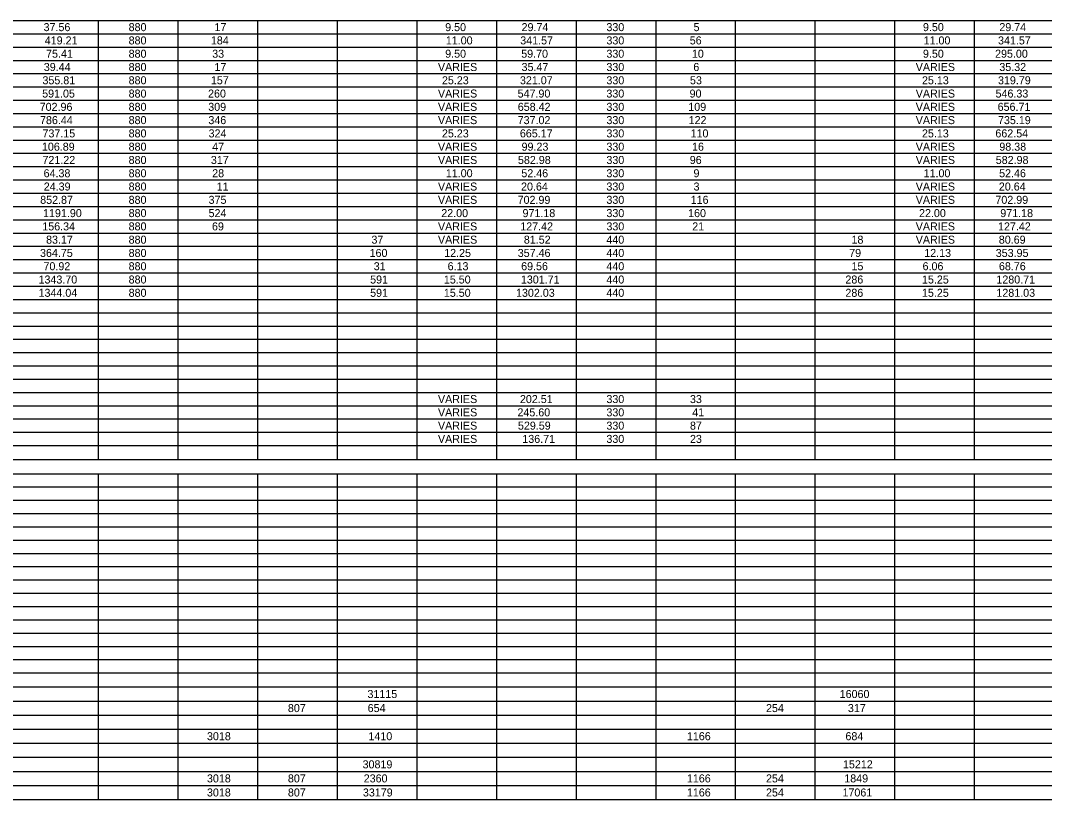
# Model space of a CAD drawing. Extents: x 1226567 to 1228151, y 151309 to 152305.
# Drawn here: x 1227158 to 1227669, y 151665 to 152053 of the extents above; entities that cross this region are included whole.
import ezdxf

# ---------------------------------------------------------------- set-up
doc = ezdxf.new("R2010")
doc.units = 0
doc.layers.add('R_Dimension', color=7, linetype='Continuous')

msp = doc.modelspace()

# ---------------------------------------------------------------- linework, layer by layer
at = {"layer": 'R_Dimension'}
for p, q in [((1226566.84, 152052.93), (1228150.79, 152052.93)), ((1227197.38, 151834.06), (1227197.38, 152052.93)), ((1227237.11, 151834.06), (1227237.11, 152052.93)), ((1227276.83, 151834.06), (1227276.83, 152052.93)), ((1227316.56, 151834.06), (1227316.56, 152052.93)), ((1227356.28, 151834.06), (1227356.28, 152052.93)), ((1227396.01, 151834.06), (1227396.01, 152052.93)), ((1227435.73, 151834.06), (1227435.73, 152052.93)), ((1227475.46, 151834.06), (1227475.46, 152052.93)), ((1227515.18, 151834.06), (1227515.18, 152052.93)), ((1227554.91, 151834.06), (1227554.91, 152052.93)), ((1227594.63, 151834.06), (1227594.63, 152052.93)), ((1227634.36, 151834.06), (1227634.36, 152052.93)), ((1226566.84, 152046.31), (1228150.79, 152046.31)), ((1226566.84, 152039.69), (1228150.79, 152039.69)), ((1226566.84, 152033.07), (1228150.79, 152033.07)), ((1226566.84, 152026.45), (1228150.79, 152026.45)), ((1226566.84, 152019.83), (1228150.79, 152019.83)), ((1226566.84, 152013.21), (1228150.79, 152013.21)), ((1226566.84, 152006.59), (1228150.79, 152006.59)), ((1226566.84, 151999.97), (1228150.79, 151999.97)), ((1226566.84, 151993.35), (1228150.79, 151993.35)), ((1226566.84, 151986.73), (1228150.79, 151986.73)), ((1226566.84, 151980.1), (1228150.79, 151980.1)), ((1226566.84, 151973.48), (1228150.79, 151973.48)), ((1226566.84, 151966.86), (1228150.79, 151966.86)), ((1226566.84, 151960.24), (1228150.79, 151960.24)), ((1226566.84, 151953.62), (1228150.79, 151953.62)), ((1226566.84, 151947), (1228150.79, 151947)), ((1226566.84, 151940.38), (1228150.79, 151940.38)), ((1226566.84, 151933.76), (1228150.79, 151933.76)), ((1226566.84, 151927.14), (1228150.79, 151927.14)), ((1226566.84, 151920.52), (1228150.79, 151920.52)), ((1226566.84, 151913.9), (1228150.79, 151913.9)), ((1226566.84, 151907.27), (1228150.79, 151907.27)), ((1226566.84, 151900.65), (1228150.79, 151900.65)), ((1226566.84, 151894.03), (1228150.79, 151894.03)), ((1226566.84, 151887.41), (1228150.79, 151887.41)), ((1226566.84, 151880.79), (1228150.79, 151880.79)), ((1226566.84, 151874.17), (1228150.79, 151874.17)), ((1226566.84, 151867.55), (1228150.79, 151867.55)), ((1226566.84, 151860.93), (1228150.79, 151860.93)), ((1226566.84, 151854.31), (1228150.79, 151854.31)), ((1226566.84, 151847.69), (1228150.79, 151847.69)), ((1226566.84, 151841.07), (1228150.79, 151841.07)), ((1226566.84, 151834.06), (1228150.79, 151834.06)), ((1226566.84, 151827.05), (1228150.79, 151827.05)), ((1227197.38, 151664.64), (1227197.38, 151827.05)), ((1227237.11, 151664.64), (1227237.11, 151827.05)), ((1227276.83, 151664.64), (1227276.83, 151827.05)), ((1227316.56, 151664.64), (1227316.56, 151827.05)), ((1227356.28, 151664.64), (1227356.28, 151827.05)), ((1227396.01, 151664.64), (1227396.01, 151827.05)), ((1227435.73, 151664.64), (1227435.73, 151827.05)), ((1227475.46, 151664.64), (1227475.46, 151827.05)), ((1227515.18, 151664.64), (1227515.18, 151827.05)), ((1227554.91, 151664.64), (1227554.91, 151827.05)), ((1227594.63, 151664.64), (1227594.63, 151827.05)), ((1227634.36, 151664.64), (1227634.36, 151827.05)), ((1226566.84, 151820.42), (1228150.79, 151820.42)), ((1226566.84, 151813.8), (1228150.79, 151813.8)), ((1226566.84, 151807.18), (1228150.79, 151807.18)), ((1226566.84, 151800.56), (1228150.79, 151800.56)), ((1226566.84, 151793.94), (1228150.79, 151793.94)), ((1226566.84, 151787.32), (1228150.79, 151787.32)), ((1226566.84, 151780.7), (1228150.79, 151780.7)), ((1226566.84, 151774.08), (1228150.79, 151774.08)), ((1226566.84, 151767.46), (1228150.79, 151767.46)), ((1226566.84, 151760.84), (1228150.79, 151760.84)), ((1226566.84, 151754.22), (1228150.79, 151754.22)), ((1226566.84, 151747.6), (1228150.79, 151747.6)), ((1226566.84, 151740.97), (1228150.79, 151740.97)), ((1226566.84, 151734.35), (1228150.79, 151734.35)), ((1226566.84, 151727.73), (1228150.79, 151727.73)), ((1226566.84, 151720.72), (1228150.79, 151720.72)), ((1226566.84, 151713.71), (1228150.79, 151713.71)), ((1226566.84, 151706.7), (1228150.79, 151706.7)), ((1226566.84, 151699.69), (1228150.79, 151699.69)), ((1226566.84, 151692.68), (1228150.79, 151692.68)), ((1226566.84, 151685.67), (1228150.79, 151685.67)), ((1226566.84, 151678.66), (1228150.79, 151678.66)), ((1226566.84, 151671.65), (1228150.79, 151671.65)), ((1226566.84, 151664.64), (1228150.79, 151664.64))]:
    msp.add_line(p, q, dxfattribs=at)

# ---------------------------------------------------------------- texts
for s, height, p in [('37.56', 3.994, (1227169.93, 152047.63)), ('880', 3.994, (1227212.36, 152047.63)), ('17', 3.994, (1227255.18, 152047.63)), ('9.50', 3.994, (1227370.28, 152047.63)), ('29.74', 3.994, (1227408.39, 152047.63)), ('330', 3.994, (1227450.71, 152047.63)), ('5', 3.99, (1227494.19, 152047.63)), ('9.50', 3.994, (1227608.63, 152047.63)), ('29.74', 3.994, (1227646.74, 152047.63)), ('419.21', 3.994, (1227170.51, 152041.01)), ('880', 3.994, (1227212.36, 152041.01)), ('184', 3.994, (1227253.39, 152041.01)), ('11.00', 3.994, (1227370.6, 152041.01)), ('341.57', 3.994, (1227407.73, 152041.01)), ('330', 3.994, (1227450.71, 152041.01)), ('56', 3.994, (1227492.29, 152041.01)), ('11.00', 3.994, (1227608.95, 152041.01)), ('341.57', 3.994, (1227646.08, 152041.01)), ('75.41', 3.994, (1227171.17, 152034.38)), ('880', 3.994, (1227212.36, 152034.38)), ('33', 3.994, (1227254.05, 152034.38)), ('9.50', 3.994, (1227370.28, 152034.38)), ('59.70', 3.994, (1227408.21, 152034.38)), ('330', 3.994, (1227450.71, 152034.38)), ('10', 3.994, (1227493.36, 152034.38)), ('9.50', 3.994, (1227608.63, 152034.38)), ('295.00', 3.994, (1227644.61, 152034.38)), ('39.44', 3.994, (1227170.04, 152027.76)), ('880', 3.994, (1227212.36, 152027.76)), ('17', 3.994, (1227255.18, 152027.76)), ('VARIES', 3.994, (1227366.68, 152027.76)), ('35.47', 3.994, (1227408.39, 152027.76)), ('330', 3.994, (1227450.71, 152027.76)), ('6', 3.99, (1227494.08, 152027.76)), ('VARIES', 3.994, (1227605.03, 152027.76)), ('35.32', 3.994, (1227646.74, 152027.76)), ('355.81', 3.994, (1227169.37, 152021.14)), ('880', 3.994, (1227212.36, 152021.14)), ('157', 3.994, (1227253.39, 152021.14)), ('25.23', 3.994, (1227368.66, 152021.14)), ('321.07', 3.994, (1227407.57, 152021.14)), ('330', 3.994, (1227450.71, 152021.14)), ('53', 3.994, (1227492.4, 152021.14)), ('25.13', 3.994, (1227608.14, 152021.14)), ('319.79', 3.994, (1227646.06, 152021.14)), ('591.05', 3.994, (1227169.22, 152014.52)), ('880', 3.994, (1227212.36, 152014.52)), ('260', 3.994, (1227251.99, 152014.52)), ('VARIES', 3.994, (1227366.68, 152014.52)), ('547.90', 3.994, (1227406.42, 152014.52)), ('330', 3.994, (1227450.71, 152014.52)), ('90', 3.994, (1227492.22, 152014.52)), ('VARIES', 3.994, (1227605.03, 152014.52)), ('546.33', 3.994, (1227644.85, 152014.52)), ('702.96', 3.994, (1227167.98, 152007.9)), ('880', 3.994, (1227212.36, 152007.9)), ('309', 3.994, (1227252.08, 152007.9)), ('VARIES', 3.994, (1227366.68, 152007.9)), ('658.42', 3.994, (1227406.5, 152007.9)), ('330', 3.994, (1227450.71, 152007.9)), ('109', 3.994, (1227491.56, 152007.9)), ('VARIES', 3.994, (1227605.03, 152007.9)), ('656.71', 3.994, (1227645.89, 152007.9)), ('786.44', 3.994, (1227168.15, 152001.28)), ('880', 3.994, (1227212.36, 152001.28)), ('346', 3.994, (1227252.14, 152001.28)), ('VARIES', 3.994, (1227366.68, 152001.28)), ('737.02', 3.994, (1227406.44, 152001.28)), ('330', 3.994, (1227450.71, 152001.28)), ('122', 3.994, (1227491.74, 152001.28)), ('VARIES', 3.994, (1227605.03, 152001.28)), ('735.19', 3.994, (1227646.06, 152001.28)), ('737.15', 3.994, (1227169.37, 151994.66)), ('880', 3.994, (1227212.36, 151994.66)), ('324', 3.994, (1227252.25, 151994.66)), ('25.23', 3.994, (1227368.66, 151994.66)), ('665.17', 3.994, (1227407.54, 151994.66)), ('330', 3.994, (1227450.71, 151994.66)), ('110', 3.994, (1227492.7, 151994.66)), ('25.13', 3.994, (1227608.14, 151994.66)), ('662.54', 3.994, (1227644.76, 151994.66)), ('106.89', 3.994, (1227169.11, 151988.04)), ('880', 3.994, (1227212.36, 151988.04)), ('47', 3.994, (1227254.05, 151988.04)), ('VARIES', 3.994, (1227366.68, 151988.04)), ('99.23', 3.994, (1227408.39, 151988.04)), ('330', 3.994, (1227450.71, 151988.04)), ('16', 3.994, (1227493.42, 151988.04)), ('VARIES', 3.994, (1227605.03, 151988.04)), ('98.38', 3.994, (1227646.74, 151988.04)), ('721.22', 3.994, (1227169.37, 151981.42)), ('880', 3.994, (1227212.36, 151981.42)), ('317', 3.994, (1227253.39, 151981.42)), ('VARIES', 3.994, (1227366.68, 151981.42)), ('582.98', 3.994, (1227406.59, 151981.42)), ('330', 3.994, (1227450.71, 151981.42)), ('96', 3.994, (1227492.29, 151981.42)), ('VARIES', 3.994, (1227605.03, 151981.42)), ('582.98', 3.994, (1227644.94, 151981.42)), ('64.38', 3.994, (1227169.94, 151974.8)), ('880', 3.994, (1227212.36, 151974.8)), ('28', 3.994, (1227254.05, 151974.8)), ('11.00', 3.994, (1227370.6, 151974.8)), ('52.46', 3.994, (1227408.28, 151974.8)), ('330', 3.994, (1227450.71, 151974.8)), ('9', 3.99, (1227494.17, 151974.8)), ('11.00', 3.994, (1227608.95, 151974.8)), ('52.46', 3.994, (1227646.63, 151974.8)), ('24.39', 3.994, (1227170.02, 151968.18)), ('880', 3.994, (1227212.36, 151968.18)), ('11', 3.994, (1227256.31, 151968.18)), ('VARIES', 3.994, (1227366.68, 151968.18)), ('20.64', 3.994, (1227408.13, 151968.18)), ('330', 3.994, (1227450.71, 151968.18)), ('3', 3.99, (1227494.19, 151968.18)), ('VARIES', 3.994, (1227605.03, 151968.18)), ('20.64', 3.994, (1227646.49, 151968.18)), ('852.87', 3.994, (1227168.24, 151961.55)), ('880', 3.994, (1227212.36, 151961.55)), ('375', 3.994, (1227252.25, 151961.55)), ('VARIES', 3.994, (1227366.68, 151961.55)), ('702.99', 3.994, (1227406.42, 151961.55)), ('330', 3.994, (1227450.71, 151961.55)), ('116', 3.994, (1227492.76, 151961.55)), ('VARIES', 3.994, (1227605.03, 151961.55)), ('702.99', 3.994, (1227644.77, 151961.55)), ('1191.90', 3.994, (1227169.67, 151954.93)), ('880', 3.994, (1227212.36, 151954.93)), ('524', 3.994, (1227252.25, 151954.93)), ('22.00', 3.994, (1227368.33, 151954.93)), ('971.18', 3.994, (1227408.86, 151954.93)), ('330', 3.994, (1227450.71, 151954.93)), ('160', 3.994, (1227491.47, 151954.93)), ('22.00', 3.994, (1227606.68, 151954.93)), ('971.18', 3.994, (1227647.21, 151954.93)), ('156.34', 3.994, (1227169.28, 151948.31)), ('880', 3.994, (1227212.36, 151948.31)), ('69', 3.994, (1227253.94, 151948.31)), ('VARIES', 3.994, (1227366.68, 151948.31)), ('127.42', 3.994, (1227407.73, 151948.31)), ('330', 3.994, (1227450.71, 151948.31)), ('21', 3.994, (1227493.53, 151948.31)), ('VARIES', 3.994, (1227605.03, 151948.31)), ('127.42', 3.994, (1227646.08, 151948.31)), ('83.17', 3.994, (1227171.17, 151941.69)), ('880', 3.994, (1227212.36, 151941.69)), ('37', 3.994, (1227333.5, 151941.69)), ('VARIES', 3.994, (1227366.68, 151941.69)), ('81.52', 3.994, (1227409.52, 151941.69)), ('440', 3.994, (1227450.71, 151941.69)), ('18', 3.994, (1227572.98, 151941.69)), ('VARIES', 3.994, (1227605.03, 151941.69)), ('80.69', 3.994, (1227646.47, 151941.69)), ('364.75', 3.994, (1227168.15, 151935.07)), ('880', 3.994, (1227212.36, 151935.07)), ('160', 3.994, (1227332.57, 151935.07)), ('12.25', 3.994, (1227369.79, 151935.07)), ('357.46', 3.994, (1227406.48, 151935.07)), ('440', 3.994, (1227450.71, 151935.07)), ('79', 3.994, (1227571.83, 151935.07)), ('12.13', 3.994, (1227609.28, 151935.07)), ('353.95', 3.994, (1227644.94, 151935.07)), ('70.92', 3.994, (1227169.88, 151928.45)), ('880', 3.994, (1227212.36, 151928.45)), ('31', 3.994, (1227334.63, 151928.45)), ('6.13', 3.994, (1227371.49, 151928.45)), ('69.56', 3.994, (1227408.18, 151928.45)), ('440', 3.994, (1227450.71, 151928.45)), ('15', 3.994, (1227572.98, 151928.45)), ('6.06', 3.994, (1227608.44, 151928.45)), ('68.76', 3.994, (1227646.53, 151928.45)), ('1343.70', 3.994, (1227167.41, 151921.83)), ('880', 3.994, (1227212.36, 151921.83)), ('591', 3.994, (1227332.84, 151921.83)), ('15.50', 3.994, (1227369.62, 151921.83)), ('1301.71', 3.994, (1227408.04, 151921.83)), ('440', 3.994, (1227450.71, 151921.83)), ('286', 3.994, (1227569.94, 151921.83)), ('15.25', 3.994, (1227608.14, 151921.83)), ('1280.71', 3.994, (1227645.26, 151921.83)), ('1344.04', 3.994, (1227167.42, 151915.21)), ('880', 3.994, (1227212.36, 151915.21)), ('591', 3.994, (1227332.84, 151915.21)), ('15.50', 3.994, (1227369.62, 151915.21)), ('1302.03', 3.994, (1227405.62, 151915.21)), ('440', 3.994, (1227450.71, 151915.21)), ('286', 3.994, (1227569.94, 151915.21)), ('15.25', 3.994, (1227608.14, 151915.21)), ('1281.03', 3.994, (1227645.26, 151915.21)), ('VARIES', 3.994, (1227366.68, 151862.24)), ('202.51', 3.994, (1227407.57, 151862.24)), ('330', 3.994, (1227450.71, 151862.24)), ('33', 3.994, (1227492.4, 151862.24)), ('VARIES', 3.994, (1227366.68, 151855.62)), ('245.60', 3.994, (1227406.33, 151855.62)), ('330', 3.994, (1227450.71, 151855.62)), ('41', 3.994, (1227493.53, 151855.62)), ('VARIES', 3.994, (1227366.68, 151849)), ('529.59', 3.994, (1227406.58, 151849)), ('330', 3.994, (1227450.71, 151849)), ('87', 3.994, (1227492.4, 151849)), ('VARIES', 3.994, (1227366.68, 151842.38)), ('136.71', 3.994, (1227408.76, 151842.38)), ('330', 3.994, (1227450.71, 151842.38)), ('23', 3.994, (1227492.4, 151842.38)), ('31115', 3.994, (1227331.51, 151715.22)), ('16060', 3.994, (1227567.08, 151715.22)), ('807', 3.994, (1227291.82, 151708.21)), ('654', 3.994, (1227331.61, 151708.21)), ('254', 3.994, (1227530.33, 151708.21)), ('317', 3.994, (1227571.19, 151708.21)), ('3018', 3.994, (1227251.44, 151694.19)), ('1410', 3.994, (1227332, 151694.19)), ('1166', 3.994, (1227490.87, 151694.19)), ('684', 3.994, (1227569.96, 151694.19)), ('30819', 3.994, (1227329.08, 151680.17)), ('15212', 3.994, (1227568.73, 151680.17)), ('3018', 3.994, (1227251.44, 151673.16)), ('807', 3.994, (1227291.82, 151673.16)), ('2360', 3.994, (1227329.64, 151673.16)), ('1166', 3.994, (1227490.87, 151673.16)), ('254', 3.994, (1227530.33, 151673.16)), ('1849', 3.994, (1227569.38, 151673.16)), ('3018', 3.994, (1227251.44, 151666.15)), ('807', 3.994, (1227291.82, 151666.15)), ('33179', 3.994, (1227329.23, 151666.15)), ('1166', 3.994, (1227490.87, 151666.15)), ('254', 3.994, (1227530.33, 151666.15)), ('17061', 3.994, (1227568.48, 151666.15))]:
    msp.add_text(s, height=height, dxfattribs=at).set_placement(p)

doc.saveas('drawing.dxf')
